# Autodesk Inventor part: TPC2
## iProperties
Shininess: 64.0
Length Units: 11272
Angle Units: 11279
Time Units: 11290
Mass Units: 11286
Length Display Precision: 3
Angle Display Precision: 2
Compacted: True
Part Number: TPC2
Document SubType Name: Modeling
Created: 2004-08
Designer: Lori
Manufacturer: Standard
Standards Organization: Custom
Density: 0.0
Volumn: 0.0
Area: 0.0
PropertySet Name: Model Information
Control State: 0
Master: False
Checked Out: False
Author: Lori
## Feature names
1. Base1
